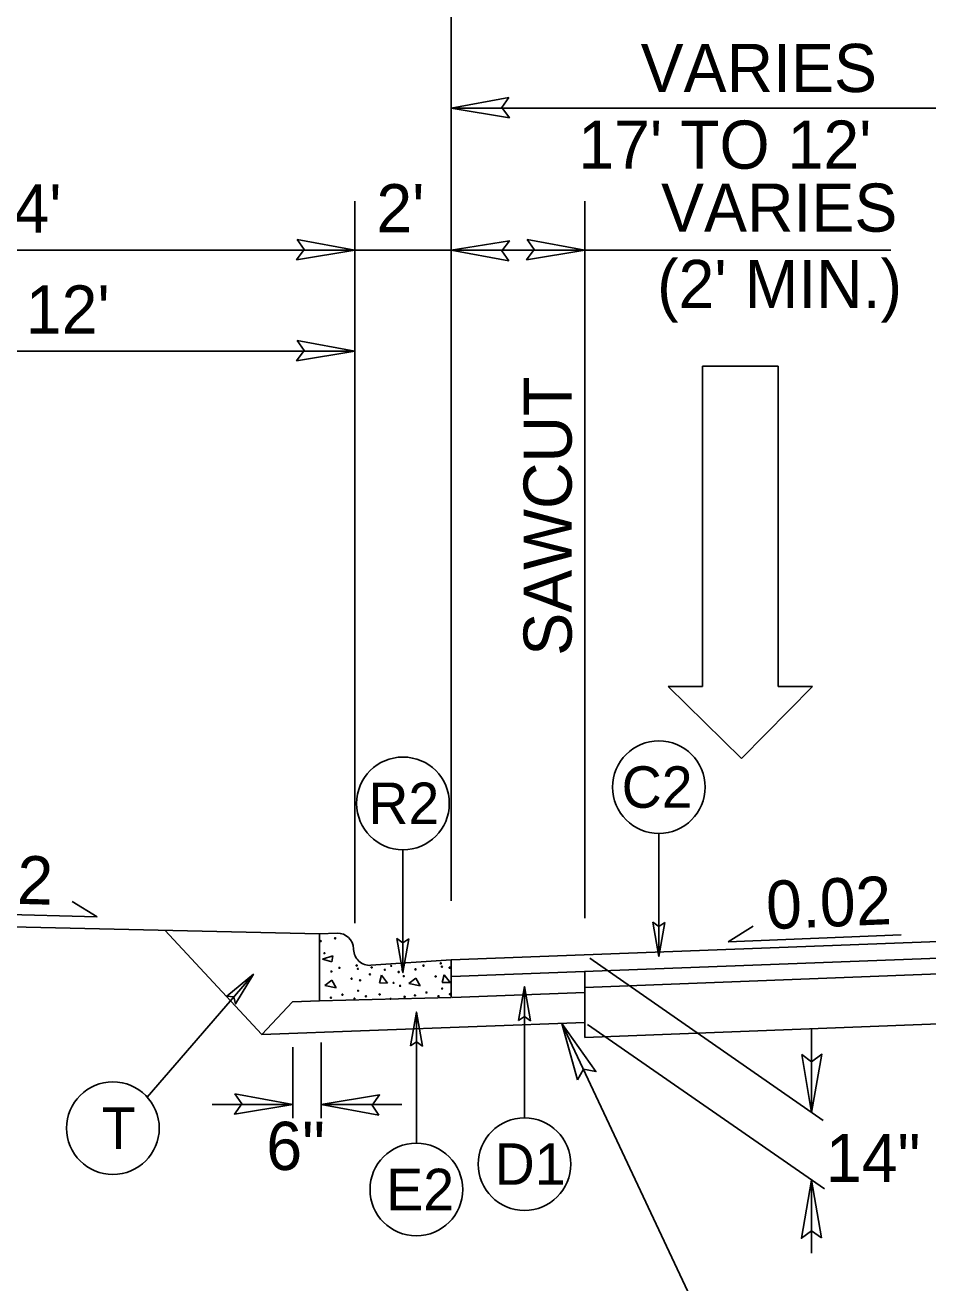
# Model space of a CAD drawing. Extents: x 573748 to 574632, y -54663 to -53209.
# Drawn here: x 574019.01 to 574047.12, y -53738.92 to -53699.76 of the extents above; entities that cross this region are included whole.
import ezdxf

# ---------------------------------------------------------------- set-up
doc = ezdxf.new("R2010")
doc.units = 0
for name, color, linetype in [('Prop Dimension', 7, 'Continuous'), ('Prop Dimension Text', 7, 'Continuous'), ('Prop Lane Arrow CELL', 7, 'Continuous'), ('Prop Terminator CELL', 7, 'Continuous'), ('Typical Arrow Superelevation CELL', 7, 'Continuous'), ('Typical Curb CELL', 7, 'Continuous'), ('Typical ID Circle CELL', 7, 'Continuous'), ('Typical Pavement Slope CELL', 7, 'Continuous'), ('Typical Terminator CELL', 7, 'Continuous'), ('Typical Text ID Circle CELL', 7, 'Continuous')]:
    doc.layers.add(name, color=color, linetype=linetype)

msp = doc.modelspace()

# ---------------------------------------------------------------- linework, layer by layer
at = {"layer": 'Prop Dimension'}
for p, q in [((574032.276, -53727.022), (574032.276, -53696.5)), ((574032.276, -53702.343), (574050.276, -53702.343)), ((574029.276, -53727.722), (574029.276, -53705.238)), ((574036.439, -53727.569), (574036.439, -53705.238)), ((574029.276, -53706.767), (574008.276, -53706.767)), ((574045.967, -53706.767), (574029.276, -53706.767)), ((574029.276, -53709.911), (574011.276, -53709.911)), ((574036.439, -53729.726), (574059.276, -53728.843)), ((574036.593, -53728.814), (574043.86, -53733.864)), ((574036.439, -53731.283), (574059.276, -53730.4)), ((574036.439, -53731.283), (574036.439, -53730.812)), ((574036.524, -53730.871), (574043.897, -53735.995)), ((574043.497, -53731.006), (574043.497, -53733.612)), ((574028.232, -53733.787), (574028.232, -53731.436)), ((574027.341, -53733.787), (574027.341, -53731.583)), ((574027.341, -53733.366), (574024.836, -53733.366)), ((574030.743, -53733.366), (574028.232, -53733.366)), ((574043.497, -53735.718), (574043.497, -53737.995))]:
    msp.add_line(p, q, dxfattribs=at)
msp.add_lwpolyline([(574042.164, -53740.907), (574040.454, -53740.907), (574035.719, -53730.839)], dxfattribs=at)
at = {"layer": 'Prop Lane Arrow CELL'}
for p, q in [((574040.101, -53720.348), (574040.101, -53710.373)), ((574040.101, -53710.373), (574042.452, -53710.373)), ((574042.452, -53710.373), (574042.452, -53720.348)), ((574041.312, -53722.592), (574039.032, -53720.348)), ((574039.032, -53720.348), (574040.101, -53720.348)), ((574043.521, -53720.348), (574041.312, -53722.592)), ((574042.452, -53720.348), (574043.521, -53720.348))]:
    msp.add_line(p, q, dxfattribs=at)
at = {"layer": 'Prop Terminator CELL'}
for points in [[(574034.073, -53702.01), (574032.276, -53702.343), (574034.091, -53702.64), (574033.857, -53702.323)], [(574027.48, -53706.434), (574029.276, -53706.767), (574027.462, -53707.064), (574027.696, -53706.747)], [(574034.643, -53706.434), (574036.439, -53706.767), (574034.625, -53707.064), (574034.859, -53706.747)], [(574034.073, -53707.1), (574032.276, -53706.767), (574034.091, -53706.47), (574033.857, -53706.787)], [(574027.48, -53709.578), (574029.276, -53709.911), (574027.462, -53710.208), (574027.696, -53709.891)], [(574036.204, -53732.601), (574035.719, -53730.839), (574036.779, -53732.341), (574036.391, -53732.269)], [(574043.187, -53731.812), (574043.497, -53733.612), (574043.817, -53731.802), (574043.497, -53732.032)], [(574025.545, -53733.032), (574027.341, -53733.366), (574025.527, -53733.663), (574025.761, -53733.345)], [(574030.028, -53733.699), (574028.232, -53733.366), (574030.046, -53733.069), (574029.812, -53733.386)], [(574043.807, -53737.518), (574043.497, -53735.718), (574043.177, -53737.528), (574043.497, -53737.298)]]:
    msp.add_lwpolyline(points, close=True, dxfattribs=at)
at = {"layer": 'Typical Arrow Superelevation CELL'}
for p, q in [((574021.251, -53727.526), (574020.472, -53727.048)), ((574021.251, -53727.526), (574015.859, -53727.384)), ((574040.899, -53728.303), (574041.672, -53727.813)), ((574040.899, -53728.303), (574046.289, -53728.079))]:
    msp.add_line(p, q, dxfattribs=at)
at = {"layer": 'Typical Curb CELL'}
for p, q in [((574028.177, -53728.047), (574028.723, -53728.033)), ((574028.177, -53730.143), (574028.177, -53728.047)), ((574028.274, -53728.837), (574028.595, -53728.735)), ((574028.595, -53728.735), (574028.565, -53728.926)), ((574029.238, -53728.544), (574029.238, -53728.521)), ((574028.565, -53728.926), (574028.274, -53728.837)), ((574032.276, -53728.863), (574029.774, -53729.032)), ((574032.276, -53730.037), (574032.276, -53728.863)), ((574028.556, -53729.498), (574028.344, -53729.661)), ((574028.693, -53729.735), (574028.556, -53729.498)), ((574030.106, -53729.34), (574030.04, -53729.58)), ((574030.292, -53729.586), (574030.106, -53729.34)), ((574031.172, -53729.43), (574030.96, -53729.593)), ((574031.309, -53729.667), (574031.172, -53729.43)), ((574032.056, -53729.325), (574031.99, -53729.565)), ((574031.99, -53729.565), (574032.244, -53729.571)), ((574032.244, -53729.571), (574032.056, -53729.325)), ((574028.344, -53729.661), (574028.693, -53729.735)), ((574030.04, -53729.58), (574030.292, -53729.586)), ((574030.96, -53729.593), (574031.309, -53729.667)), ((574027.34, -53730.165), (574028.177, -53730.143)), ((574028.177, -53730.143), (574032.276, -53730.037))]:
    msp.add_line(p, q, dxfattribs=at)
for centre in [(574028.211, -53728.277), (574028.664, -53728.193), (574028.329, -53728.657), (574028.796, -53729.111), (574029.332, -53729.037), (574029.371, -53729.142), (574029.8, -53729.097), (574030.21, -53729.169), (574030.41, -53729.05), (574030.758, -53729.166), (574031.164, -53729.156), (574031.413, -53729.043), (574031.95, -53728.97), (574031.988, -53729.074), (574032.227, -53729.105), (574028.547, -53729.224), (574029.175, -53729.447), (574029.44, -53729.5), (574029.746, -53729.312), (574030.483, -53729.58), (574030.642, -53729.241), (574030.799, -53729.369), (574031.792, -53729.379), (574028.889, -53729.945), (574029.377, -53729.824), (574030.05, -53729.939), (574030.687, -53729.671), (574031.15, -53729.97), (574031.506, -53729.877), (574031.994, -53729.757), (574032.238, -53729.93), (574028.532, -53730.038), (574029.263, -53730.067), (574029.621, -53729.998), (574030.388, -53730.073), (574030.828, -53730.014), (574031.88, -53729.999)]:
    msp.add_circle(centre, 0.0168, dxfattribs=at)
for centre, start, end in [((574028.736, -53728.534), 1.4804, 91.4804), ((574029.74, -53728.531), 181.4804, 273.8649)]:
    msp.add_arc(centre, 0.502, start, end, dxfattribs=at)
at = {"layer": 'Typical ID Circle CELL'}
for p, q in [((574038.741, -53724.927), (574038.741, -53728.753)), ((574030.775, -53725.433), (574030.775, -53729.26)), ((574022.811, -53733.133), (574026.117, -53729.311)), ((574034.557, -53733.78), (574034.557, -53729.696)), ((574031.192, -53734.571), (574031.192, -53730.488))]:
    msp.add_line(p, q, dxfattribs=at)
for centre in [(574038.741, -53723.484), (574030.775, -53723.991), (574021.744, -53734.104), (574034.557, -53735.222), (574031.192, -53736.014)]:
    msp.add_circle(centre, 1.443, dxfattribs=at)
at = {"layer": 'Typical Pavement Slope CELL'}
for p, q in [((574028.177, -53728.047), (574008.276, -53727.607)), ((574026.386, -53731.188), (574023.359, -53727.94)), ((574051.776, -53728.133), (574032.276, -53728.863)), ((574059.276, -53728.367), (574032.29, -53729.376)), ((574036.439, -53730.812), (574036.439, -53729.221)), ((574036.439, -53729.882), (574032.307, -53730.036)), ((574026.386, -53731.188), (574027.34, -53730.165)), ((574036.439, -53730.812), (574026.386, -53731.188))]:
    msp.add_line(p, q, dxfattribs=at)
at = {"layer": 'Typical Terminator CELL'}
for points in [[(574038.923, -53727.698), (574038.741, -53728.753), (574038.554, -53727.693), (574038.741, -53727.827)], [(574030.957, -53728.205), (574030.775, -53729.26), (574030.587, -53728.199), (574030.775, -53728.334)], [(574025.289, -53729.99), (574026.117, -53729.311), (574025.565, -53730.236), (574025.511, -53730.011)], [(574034.375, -53730.751), (574034.557, -53729.696), (574034.744, -53730.756), (574034.557, -53730.622)], [(574031.01, -53731.542), (574031.192, -53730.488), (574031.379, -53731.548), (574031.192, -53731.413)]]:
    msp.add_lwpolyline(points, close=True, dxfattribs=at)

# ---------------------------------------------------------------- texts
at = {"layer": 'Prop Dimension Text'}
for s, p in [('VARIES', (574038.173, -53701.842)), ("17' TO 12'", (574036.232, -53704.229)), ("14'", (574017.532, -53706.217)), ("2'", (574029.946, -53706.21)), ('VARIES', (574038.809, -53706.19)), ("(2' MIN.)", (574038.686, -53708.569)), ("12'", (574019.032, -53709.362)), ('6"', (574026.52, -53735.404)), ('14"', (574043.941, -53735.78))]:
    msp.add_text(s, height=1.5, dxfattribs=at).set_placement(p)
for s, rotation, p in [('SAWCUT', 90, (574036.028, -53719.394)), ('0.02', 358.4883, (574015.959, -53727.044)), ('0.02', 2.3757, (574042.109, -53727.91))]:
    msp.add_text(s, height=1.5, rotation=rotation, dxfattribs=at).set_placement(p)
at = {"layer": 'Typical Text ID Circle CELL'}
for s, height, p in [('C2', 1.2912, (574037.583, -53724.127)), ('R2', 1.2912, (574029.697, -53724.634)), ('T', 1.291, (574021.394, -53734.747)), ('D1', 1.2912, (574033.629, -53735.865)), ('E2', 1.2912, (574030.254, -53736.657))]:
    msp.add_text(s, height=height, dxfattribs=at).set_placement(p)

doc.saveas('drawing.dxf')
